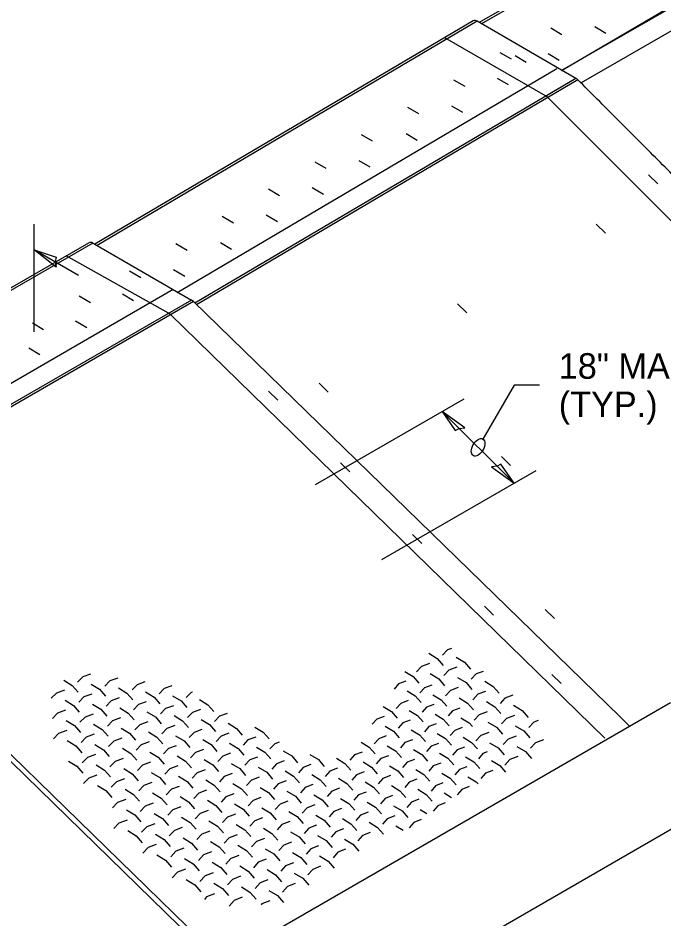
# Model space of a CAD drawing. Extents: x 99862 to 103151, y 100000 to 102076.
# Drawn here: x 101226 to 101630, y 101228 to 101791 of the extents above; entities that cross this region are included whole.
import ezdxf

# ---------------------------------------------------------------- set-up
doc = ezdxf.new("R2010")
doc.units = 0
for name, color, linetype in [('Level 11', 7, 'Continuous'), ('Level 15', 7, 'Continuous'), ('Level 20', 7, 'Continuous'), ('Level 3', 7, 'Continuous'), ('Level 36', 7, 'Continuous'), ('Level 4', 7, 'Continuous'), ('Level 5', 7, 'Continuous'), ('Level 7', 7, 'Continuous')]:
    doc.layers.add(name, color=color, linetype=linetype)

msp = doc.modelspace()

# ---------------------------------------------------------------- linework, layer by layer
at = {"layer": 'Level 11'}
for points in [[(101483.29, 101393.94), (101488.6, 101390.69), (101492.28, 101386.41)], [(101497.51, 101397), (101494.97, 101396.07), (101491.83, 101392.75)], [(101483.73, 101387.59), (101478.77, 101385.75), (101475.59, 101382.4)], [(101500.35, 101391.57), (101505.65, 101388.32), (101509.34, 101384.05)], [(101271.83, 101380.92), (101266.86, 101379.16), (101263.67, 101375.91)], [(101468.35, 101382.52), (101473.46, 101379.4), (101477.1, 101375.3)], [(101484.17, 101381.22), (101489.49, 101377.96), (101493.19, 101373.66)], [(101500.82, 101385.23), (101495.88, 101383.39), (101492.74, 101380.04)], [(101517.26, 101382.65), (101512.93, 101381.04), (101509.82, 101377.69)], [(101255.11, 101377.14), (101260.39, 101373.91), (101264.03, 101369.67)], [(101288.84, 101378.47), (101283.9, 101376.72), (101280.74, 101373.47)], [(101305.79, 101376.03), (101300.88, 101374.28), (101297.74, 101371.04)], [(101469.02, 101376.49), (101464.42, 101374.78), (101461.57, 101371.62)], [(101501.28, 101378.87), (101506.6, 101375.62), (101510.3, 101371.32)], [(101518.33, 101376.52), (101523.63, 101373.28), (101527.33, 101368.99)], [(101255.46, 101370.89), (101250.45, 101369.11), (101247.21, 101365.83)], [(101272.21, 101374.69), (101277.48, 101371.46), (101281.13, 101367.23)], [(101289.25, 101372.25), (101294.51, 101369.03), (101298.16, 101364.8)], [(101306.22, 101369.82), (101311.47, 101366.61), (101315.12, 101362.39)], [(101322.67, 101373.6), (101317.79, 101371.85), (101314.68, 101368.61)], [(101335.45, 101369.73), (101334.63, 101369.43), (101331.55, 101366.2)], [(101469.68, 101370.43), (101474.81, 101367.3), (101478.46, 101363.18)], [(101485.17, 101374.12), (101480.6, 101372.41), (101477.78, 101369.25)], [(101501.75, 101372.49), (101496.8, 101370.63), (101493.65, 101367.26)], [(101518.82, 101370.15), (101513.9, 101368.3), (101510.78, 101364.93)], [(101255.81, 101364.61), (101261.11, 101361.37), (101264.77, 101357.11)], [(101272.59, 101368.45), (101267.61, 101366.67), (101264.4, 101363.4)], [(101289.65, 101366.02), (101284.7, 101364.24), (101281.52, 101360.97)], [(101306.65, 101363.59), (101301.72, 101361.82), (101298.58, 101358.55)], [(101323.12, 101367.4), (101328.36, 101364.19), (101332.02, 101359.98)], [(101339.96, 101364.99), (101345.19, 101361.79), (101348.85, 101357.58)], [(101470.35, 101364.36), (101465.75, 101362.64), (101462.89, 101359.45)], [(101485.86, 101368.07), (101490.98, 101364.94), (101494.63, 101360.84)], [(101502.22, 101366.09), (101507.55, 101362.83), (101511.26, 101358.51)], [(101519.32, 101363.76), (101524.64, 101360.51), (101528.35, 101356.2)], [(101535.83, 101367.83), (101530.94, 101365.97), (101527.84, 101362.6)], [(101256.17, 101358.32), (101251.14, 101356.52), (101247.89, 101353.22)], [(101272.97, 101362.18), (101278.26, 101358.94), (101281.91, 101354.69)], [(101290.06, 101359.76), (101295.34, 101356.53), (101299, 101352.28)], [(101323.58, 101361.18), (101318.68, 101359.41), (101315.56, 101356.14)], [(101340.44, 101358.78), (101335.58, 101357.01), (101332.49, 101353.74)], [(101454.74, 101360.63), (101459.9, 101357.48), (101463.55, 101353.33)], [(101471.02, 101358.27), (101476.17, 101355.13), (101479.83, 101350.99)], [(101486.55, 101362.01), (101481.97, 101360.28), (101479.14, 101357.1)], [(101502.69, 101359.67), (101498.14, 101357.94), (101495.34, 101354.76)], [(101536.35, 101361.45), (101541.66, 101358.2), (101545.38, 101353.89)], [(101273.35, 101355.9), (101268.35, 101354.1), (101265.14, 101350.8)], [(101290.46, 101353.48), (101285.5, 101351.69), (101282.31, 101348.39)], [(101307.08, 101357.35), (101312.35, 101354.12), (101316.01, 101349.88)], [(101324.03, 101354.94), (101329.29, 101351.72), (101332.96, 101347.49)], [(101340.92, 101352.55), (101346.18, 101349.33), (101349.84, 101345.11)], [(101357.24, 101356.39), (101352.41, 101354.62), (101349.35, 101351.35)], [(101455.39, 101354.51), (101450.74, 101352.76), (101447.85, 101349.55)], [(101471.7, 101352.16), (101467.08, 101350.42), (101464.22, 101347.2)], [(101487.25, 101355.93), (101492.38, 101352.79), (101496.04, 101348.66)], [(101503.41, 101353.59), (101508.54, 101350.46), (101510.66, 101348.07)], [(101519.82, 101357.35), (101514.88, 101355.48), (101511.75, 101352.07)], [(101536.87, 101355.05), (101531.97, 101353.17), (101528.86, 101349.77)], [(101256.52, 101352.01), (101261.84, 101348.75), (101265.51, 101344.47)], [(101273.73, 101349.59), (101279.04, 101346.34), (101282.71, 101342.07)], [(101290.87, 101347.19), (101296.17, 101343.94), (101299.84, 101339.68)], [(101307.51, 101351.08), (101302.57, 101349.28), (101299.42, 101345.99)], [(101324.49, 101348.68), (101319.59, 101346.89), (101316.46, 101343.6)], [(101357.75, 101350.16), (101362.99, 101346.96), (101366.66, 101342.74)], [(101374.51, 101347.79), (101379.74, 101344.59), (101383.41, 101340.37)], [(101456.04, 101348.37), (101461.21, 101345.21), (101464.88, 101341.05)], [(101487.94, 101349.83), (101483.35, 101348.08), (101480.52, 101344.87)], [(101504.13, 101347.5), (101499.57, 101345.75), (101496.76, 101342.54)], [(101520.31, 101350.92), (101525.65, 101347.65), (101529.38, 101343.32)], [(101537.4, 101348.62), (101542.72, 101345.36), (101546.45, 101341.04)], [(101551.71, 101351.92), (101548.99, 101350.87), (101545.91, 101347.48)], [(101256.88, 101345.67), (101251.84, 101343.86), (101248.58, 101340.52)], [(101274.11, 101343.27), (101269.1, 101341.45), (101265.88, 101338.12)], [(101291.28, 101340.87), (101286.3, 101339.06), (101283.1, 101335.73)], [(101307.95, 101344.79), (101313.23, 101341.55), (101316.91, 101337.29)], [(101324.95, 101342.4), (101330.23, 101339.17), (101333.91, 101334.92)], [(101341.41, 101346.3), (101336.53, 101344.5), (101333.43, 101341.21)], [(101358.26, 101343.92), (101353.41, 101342.13), (101350.34, 101338.84)], [(101375.05, 101341.55), (101370.23, 101339.76), (101367.18, 101336.48)], [(101456.7, 101342.22), (101452.04, 101340.45), (101449.14, 101337.21)], [(101472.37, 101346.03), (101477.54, 101342.88), (101481.21, 101338.73)], [(101488.64, 101343.71), (101493.8, 101340.56), (101497.47, 101336.41)], [(101504.85, 101341.38), (101510, 101338.24), (101513.67, 101334.1)], [(101520.83, 101344.5), (101515.89, 101342.62), (101512.76, 101339.22)], [(101537.92, 101342.18), (101533.01, 101340.28), (101529.89, 101336.86)], [(101257.24, 101339.32), (101262.57, 101336.05), (101266.25, 101331.75)], [(101274.5, 101336.92), (101279.82, 101333.66), (101283.5, 101329.37)], [(101308.38, 101338.48), (101303.43, 101336.67), (101300.26, 101333.34)], [(101325.42, 101336.1), (101320.49, 101334.29), (101317.36, 101330.97)], [(101341.9, 101340.03), (101347.16, 101336.8), (101350.84, 101332.55)], [(101358.77, 101337.66), (101364.03, 101334.44), (101367.71, 101330.2)], [(101375.58, 101335.3), (101380.83, 101332.09), (101384.51, 101327.85)], [(101389.75, 101338.44), (101386.98, 101337.4), (101383.96, 101334.12)], [(101440.91, 101338.37), (101446.11, 101335.2), (101449.79, 101331.01)], [(101457.35, 101336.04), (101462.54, 101332.87), (101466.22, 101328.69)], [(101473.05, 101339.89), (101468.42, 101338.12), (101465.55, 101334.88)], [(101489.35, 101337.57), (101484.74, 101335.8), (101481.9, 101332.56)], [(101505.58, 101335.25), (101501, 101333.49), (101498.19, 101330.26)], [(101521.34, 101338.01), (101526.68, 101334.74), (101530.41, 101330.41)], [(101538.45, 101335.72), (101543.79, 101332.44), (101547.54, 101328.1)], [(101554.97, 101339.9), (101550.08, 101338), (101546.99, 101334.58)], [(101274.89, 101330.56), (101269.86, 101328.72), (101266.62, 101325.36)], [(101291.69, 101334.53), (101297.01, 101331.28), (101300.69, 101326.99)], [(101308.82, 101332.16), (101314.12, 101328.91), (101317.81, 101324.63)], [(101325.88, 101329.79), (101331.17, 101326.54), (101334.86, 101322.27)], [(101342.38, 101333.74), (101337.49, 101331.92), (101334.38, 101328.6)], [(101359.28, 101331.38), (101354.42, 101329.56), (101351.34, 101326.25)], [(101392.33, 101332.95), (101397.57, 101329.74), (101401.25, 101325.52)], [(101409.01, 101330.61), (101414.24, 101327.41), (101417.93, 101323.19)], [(101441.55, 101332.17), (101436.84, 101330.38), (101433.91, 101327.11)], [(101458.01, 101329.85), (101453.34, 101328.06), (101450.43, 101324.79)], [(101473.73, 101333.72), (101478.91, 101330.56), (101482.59, 101326.38)], [(101490.05, 101331.41), (101495.22, 101328.25), (101498.9, 101324.08)], [(101519.84, 101332.21), (101517.2, 101331.19), (101514.41, 101327.96)], [(101257.96, 101326.55), (101263.31, 101323.28), (101267, 101318.95)], [(101275.27, 101324.17), (101280.61, 101320.9), (101284.31, 101316.58)], [(101292.11, 101328.18), (101287.11, 101326.34), (101283.9, 101322.99)], [(101309.26, 101325.81), (101304.29, 101323.97), (101301.12, 101320.62)], [(101342.87, 101327.43), (101348.16, 101324.19), (101351.85, 101319.92)], [(101359.8, 101325.07), (101365.07, 101321.84), (101368.77, 101317.58)], [(101376.12, 101329.02), (101371.29, 101327.21), (101368.24, 101323.9)], [(101392.89, 101326.68), (101388.09, 101324.87), (101385.07, 101321.56)], [(101409.6, 101324.35), (101404.83, 101322.54), (101401.83, 101319.24)], [(101425.63, 101328.28), (101430.85, 101325.08), (101434.54, 101320.87)], [(101442.18, 101325.95), (101447.39, 101322.76), (101451.08, 101318.56)], [(101474.41, 101327.54), (101469.77, 101325.75), (101466.89, 101322.48)], [(101490.76, 101325.23), (101486.14, 101323.45), (101483.29, 101320.18)], [(101506.31, 101329.1), (101511.46, 101325.95), (101515.15, 101321.79)], [(101522.5, 101326.81), (101527.65, 101323.66), (101531.34, 101319.51)], [(101538.97, 101329.29), (101534.04, 101327.41), (101530.9, 101324.01)], [(101292.52, 101321.8), (101297.85, 101318.54), (101301.55, 101314.23)], [(101309.7, 101319.44), (101315.02, 101316.18), (101318.72, 101311.88)], [(101326.34, 101323.45), (101321.41, 101321.61), (101318.26, 101318.26)], [(101343.36, 101321.09), (101338.46, 101319.26), (101335.34, 101315.91)], [(101360.32, 101318.75), (101355.44, 101316.92), (101352.35, 101313.58)], [(101376.66, 101322.73), (101381.93, 101319.51), (101385.62, 101315.26)], [(101393.46, 101320.4), (101398.71, 101317.18), (101402.41, 101312.94)], [(101426.24, 101322.03), (101421.5, 101320.22), (101418.53, 101316.92)], [(101442.82, 101319.71), (101438.11, 101317.9), (101435.17, 101314.6)], [(101458.67, 101323.64), (101463.87, 101320.46), (101467.57, 101316.26)], [(101475.1, 101321.33), (101480.29, 101318.16), (101483.99, 101313.96)], [(101491.46, 101319.04), (101496.65, 101315.87), (101500.35, 101311.68)], [(101507.04, 101322.94), (101502.45, 101321.15), (101499.62, 101317.89)], [(101523.25, 101320.65), (101518.69, 101318.86), (101515.9, 101315.61)], [(101275.66, 101317.77), (101270.62, 101315.91), (101267.37, 101312.52)], [(101292.93, 101315.4), (101287.92, 101313.55), (101284.71, 101310.16)], [(101310.14, 101313.05), (101305.16, 101311.2), (101301.97, 101307.81)], [(101326.81, 101317.09), (101332.12, 101313.84), (101335.82, 101309.54)], [(101343.85, 101314.74), (101349.16, 101311.5), (101352.86, 101307.21)], [(101377.2, 101316.42), (101372.36, 101314.59), (101369.3, 101311.25)], [(101394.02, 101314.09), (101389.21, 101312.26), (101386.18, 101308.93)], [(101410.19, 101318.07), (101415.44, 101314.86), (101419.14, 101310.62)], [(101426.86, 101315.76), (101432.09, 101312.55), (101435.79, 101308.32)], [(101443.46, 101313.45), (101448.69, 101310.25), (101452.39, 101306.03)], [(101459.33, 101317.41), (101454.65, 101315.6), (101451.74, 101312.3)], [(101475.79, 101315.11), (101471.13, 101313.3), (101468.24, 101310.01)], [(101492.17, 101312.82), (101487.55, 101311.01), (101484.69, 101307.73)], [(101507.77, 101316.75), (101512.94, 101313.58), (101514.17, 101312.2)], [(101276.05, 101311.34), (101281.41, 101308.06), (101285.11, 101303.72)], [(101293.35, 101308.99), (101298.7, 101305.71), (101302.41, 101301.38)], [(101327.28, 101310.71), (101322.33, 101308.85), (101319.17, 101305.48)], [(101344.35, 101308.37), (101339.43, 101306.52), (101336.3, 101303.15)], [(101360.83, 101312.41), (101366.12, 101309.17), (101369.83, 101304.89)], [(101377.75, 101310.09), (101383.03, 101306.85), (101386.74, 101302.58)], [(101394.59, 101307.77), (101399.87, 101304.54), (101403.58, 101300.28)], [(101410.78, 101311.78), (101406, 101309.95), (101402.99, 101306.62)], [(101427.47, 101309.47), (101422.72, 101307.64), (101419.74, 101304.31)], [(101444.1, 101307.17), (101439.37, 101305.34), (101436.43, 101302.02)], [(101460, 101311.16), (101465.22, 101307.96), (101468.92, 101303.74)], [(101476.47, 101308.87), (101481.68, 101305.68), (101485.39, 101301.47)], [(101508.5, 101310.54), (101503.9, 101308.74), (101501.07, 101305.45)], [(101293.77, 101302.55), (101288.74, 101300.67), (101285.52, 101297.26)], [(101310.58, 101306.64), (101315.92, 101303.37), (101319.63, 101299.05)], [(101327.75, 101304.31), (101333.07, 101301.05), (101336.79, 101296.73)], [(101344.84, 101301.98), (101350.16, 101298.73), (101353.88, 101294.42)], [(101361.35, 101306.05), (101356.46, 101304.19), (101353.37, 101300.82)], [(101378.29, 101303.73), (101373.43, 101301.88), (101370.36, 101298.51)], [(101395.16, 101301.43), (101390.33, 101299.57), (101387.3, 101296.21)], [(101411.38, 101305.46), (101416.64, 101302.24), (101420.35, 101297.98)], [(101428.09, 101303.16), (101433.35, 101299.95), (101437.06, 101295.7)], [(101460.66, 101304.89), (101455.97, 101303.06), (101453.05, 101299.73)], [(101477.17, 101302.6), (101472.5, 101300.78), (101469.6, 101297.46)], [(101492.89, 101306.59), (101497.56, 101303.73)], [(101294.19, 101296.09), (101299.55, 101292.81), (101303.27, 101288.45)], [(101311.03, 101300.22), (101306.03, 101298.34), (101302.84, 101294.93)], [(101328.22, 101297.89), (101323.25, 101296.01), (101320.09, 101292.61)], [(101361.87, 101299.67), (101367.18, 101296.42), (101370.9, 101292.11)], [(101378.84, 101297.36), (101384.14, 101294.12), (101387.86, 101289.82)], [(101411.97, 101299.13), (101407.17, 101297.27), (101404.16, 101293.92)], [(101428.71, 101296.84), (101423.94, 101294.99), (101420.96, 101291.63)], [(101444.74, 101300.88), (101449.99, 101297.67), (101453.71, 101293.42)], [(101461.33, 101298.6), (101466.57, 101295.39), (101470.29, 101291.15)], [(101477.86, 101296.32), (101482.16, 101293.69)], [(101493.6, 101300.33), (101488.96, 101298.51), (101486.1, 101295.19)], [(101311.47, 101293.77), (101316.83, 101290.49), (101320.55, 101286.14)], [(101328.69, 101291.45), (101334.03, 101288.18), (101337.76, 101283.84)], [(101345.34, 101295.57), (101340.41, 101293.7), (101337.27, 101290.29)], [(101362.4, 101293.27), (101357.49, 101291.39), (101354.39, 101287.99)], [(101379.39, 101290.97), (101374.51, 101289.09), (101371.44, 101285.7)], [(101395.74, 101295.06), (101401.03, 101291.82), (101404.75, 101287.54)], [(101412.57, 101292.77), (101417.85, 101289.54), (101421.57, 101285.26)], [(101429.34, 101290.49), (101434.61, 101287.27), (101438.33, 101282.99)], [(101445.39, 101294.56), (101440.65, 101292.71), (101437.7, 101289.35)], [(101462, 101292.29), (101457.29, 101290.44), (101454.37, 101287.09)], [(101294.61, 101289.61), (101289.57, 101287.71), (101286.33, 101284.27)], [(101311.92, 101287.3), (101306.91, 101285.4), (101303.71, 101281.96)], [(101329.16, 101284.99), (101324.18, 101283.09), (101321.01, 101279.66)], [(101345.84, 101289.14), (101351.17, 101285.87), (101354.9, 101281.54)], [(101362.92, 101286.84), (101368.25, 101283.58), (101371.98, 101279.26)], [(101379.94, 101284.55), (101385.25, 101281.3), (101388.99, 101276.98)], [(101396.31, 101288.68), (101391.47, 101286.8), (101388.42, 101283.41)], [(101413.17, 101286.4), (101408.36, 101284.52), (101405.34, 101281.14)], [(101446.04, 101288.22), (101451.3, 101285), (101455.03, 101280.73)], [(101462.68, 101285.96), (101467.18, 101283.2)], [(101478.55, 101290.02), (101473.87, 101288.17), (101470.97, 101284.83)], [(101295.03, 101283.11), (101300.41, 101279.82), (101304.14, 101275.44)], [(101312.37, 101280.81), (101317.74, 101277.51), (101321.48, 101273.15)], [(101346.34, 101282.69), (101341.39, 101280.79), (101338.25, 101277.36)], [(101363.45, 101280.4), (101358.53, 101278.5), (101355.42, 101275.08)], [(101396.89, 101282.27), (101402.19, 101279.02), (101405.93, 101274.72)], [(101413.77, 101280), (101419.07, 101276.76), (101422.8, 101272.46)], [(101429.96, 101284.12), (101425.18, 101282.25), (101422.19, 101278.87)], [(101446.69, 101281.86), (101441.93, 101279.99), (101438.97, 101276.61)], [(101312.82, 101274.29), (101307.79, 101272.37), (101304.58, 101268.91)], [(101329.64, 101278.51), (101335, 101275.22), (101338.74, 101270.86)], [(101346.84, 101276.22), (101352.19, 101272.94), (101355.93, 101268.59)], [(101363.98, 101273.94), (101369.32, 101270.66), (101373.06, 101266.32)], [(101380.49, 101278.12), (101375.6, 101276.22), (101372.52, 101272.8)], [(101397.47, 101275.85), (101392.61, 101273.95), (101389.55, 101270.53)], [(101414.37, 101273.58), (101409.55, 101271.69), (101406.52, 101268.27)], [(101430.59, 101277.74), (101435.88, 101274.5), (101439.61, 101270.21)], [(101313.27, 101267.76), (101318.66, 101264.46), (101322.41, 101260.07)], [(101330.12, 101272), (101325.12, 101270.08), (101321.94, 101266.62)], [(101347.34, 101269.72), (101342.38, 101267.8), (101339.23, 101264.35)], [(101381.04, 101271.67), (101386.38, 101268.4), (101390.12, 101264.06)], [(101398.05, 101269.4), (101403.37, 101266.14), (101407.12, 101261.81)], [(101431.22, 101271.33), (101426.42, 101269.44), (101423.42, 101266.03)], [(101330.59, 101265.48), (101335.97, 101262.19), (101339.72, 101257.81)], [(101347.85, 101263.21), (101353.22, 101259.92), (101356.97, 101255.55)], [(101364.51, 101267.45), (101359.57, 101265.53), (101356.45, 101262.08)], [(101381.6, 101265.19), (101376.7, 101263.27), (101373.61, 101259.82)], [(101398.63, 101262.94), (101393.76, 101261.02), (101390.69, 101257.57)], [(101414.98, 101267.15), (101420.29, 101263.9), (101424.04, 101259.57)], [(101331.07, 101258.94), (101326.06, 101256.99), (101322.87, 101253.5)], [(101348.36, 101256.68), (101343.38, 101254.73), (101340.22, 101251.25)], [(101365.04, 101260.95), (101370.4, 101257.67), (101374.15, 101253.3)], [(101382.16, 101258.7), (101387.51, 101255.42), (101391.26, 101251.06)], [(101399.21, 101256.45), (101404.55, 101253.18), (101408.31, 101248.83)], [(101415.59, 101260.69), (101410.75, 101258.78), (101407.71, 101255.33)], [(101331.56, 101252.37), (101336.95, 101249.07), (101340.71, 101244.66)], [(101365.57, 101254.42), (101360.62, 101252.48), (101357.49, 101249)], [(101382.72, 101252.18), (101377.8, 101250.24), (101374.7, 101246.76)], [(101348.86, 101250.12), (101354.25, 101246.82), (101358.02, 101242.43)], [(101366.11, 101247.88), (101371.48, 101244.58), (101375.25, 101240.2)], [(101383.28, 101245.64), (101388.64, 101242.35), (101392.41, 101237.97)], [(101399.8, 101249.94), (101394.91, 101248), (101391.84, 101244.53)], [(101349.37, 101243.54), (101344.38, 101241.58), (101342.96, 101239.99)], [(101366.64, 101241.31), (101361.68, 101239.34), (101358.54, 101235.83)], [(101383.84, 101239.08), (101378.91, 101237.12), (101378.42, 101236.57)]]:
    msp.add_lwpolyline(points, dxfattribs=at)
at = {"layer": 'Level 15'}
for p, q in [((101236.6, 101595.01), (101236.6, 101662.51)), ((101264.17, 101630.26), (101236.6, 101646.51)), ((101536.59, 101561.75), (101517.11, 101528.02)), ((101552.59, 101561.75), (101536.59, 101561.75)), ((101412.41, 101499.51), (101505.48, 101553.25)), ((101491.62, 101545.25), (101536.6, 101500.41)), ((101453.91, 101452.67), (101550.46, 101508.41))]:
    msp.add_line(p, q, dxfattribs=at)
for points in [[(101236.6, 101646.51), (101250.22, 101641.73), (101249.59, 101639.01), (101250.22, 101635.56)], [(101491.62, 101545.25), (101499.78, 101533.34), (101502.25, 101534.65), (101505.74, 101534.94)], [(101536.6, 101500.41), (101528.44, 101512.31), (101525.98, 101511), (101522.48, 101510.71)]]:
    msp.add_lwpolyline(points, close=True, dxfattribs=at)
msp.add_ellipse((101514.11, 101522.83), major_axis=(3, 5.2), ratio=0.57735, dxfattribs=at)
at = {"layer": 'Level 3'}
for p, q in [((101273.2, 101650.61), (101018.64, 101503.64)), ((101030.62, 101512.24), (101270.7, 101650.85)), ((101273.2, 101650.61), (101274.41, 101649.9)), ((101274.41, 101649.9), (101334.93, 101614.92)), ((101334.93, 101614.92), (101080.37, 101467.95)), ((101336.08, 101614.04), (101081.52, 101467.07)), ((101336.08, 101614.04), (101602.84, 101354.32)), ((101348.28, 101207.36), (101081.52, 101467.07)), ((101081.55, 101462.94), (101347.07, 101204.22)), ((101634.49, 101362.93), (101379.93, 101215.96)), ((101602.84, 101354.32), (101608.98, 101348.2)), ((101413.08, 101155.93), (101667.64, 101302.9)), ((101413.08, 101155.93), (101667.64, 101302.9))]:
    msp.add_line(p, q, dxfattribs=at)
for centre, start_param, end_param in [((101273.2, 101646.52), 2.356194, 3.141593), ((101334.93, 101610.84), 2.025645, 2.356194)]:
    msp.add_ellipse(centre, major_axis=(2.5, -4.33), ratio=0.57735, start_param=start_param, end_param=end_param, dxfattribs=at)
at = {"layer": 'Level 36'}
for p, q in [((101559.62, 101785.33), (101566.57, 101781.23)), ((101587.14, 101786.18), (101594.1, 101782.08)), ((101527.79, 101769.93), (101534.75, 101765.83)), ((101537.24, 101768.04), (101544.19, 101763.94)), ((101557.87, 101769.28), (101564.83, 101765.18)), ((101498.85, 101752.84), (101505.81, 101748.74)), ((101526.07, 101753.87), (101533.02, 101749.77)), ((101469.91, 101735.75), (101476.86, 101731.65)), ((101497.5, 101736.56), (101504.46, 101732.46)), ((101440.96, 101718.67), (101447.92, 101714.57)), ((101469.05, 101719.18), (101476, 101715.08)), ((101439.57, 101702.41), (101446.53, 101698.31)), ((101412.02, 101701.58), (101418.97, 101697.48)), ((101620.68, 101693.25), (101626.47, 101687.62)), ((101410.41, 101685.45), (101417.37, 101681.35)), ((101383.07, 101684.49), (101390.03, 101680.39)), ((101381.65, 101668.25), (101388.61, 101664.15)), ((101354.13, 101667.41), (101361.09, 101663.3)), ((101588.04, 101662.58), (101593.83, 101656.95)), ((101353.03, 101650.98), (101359.98, 101646.88)), ((101325.19, 101650.32), (101332.14, 101646.22)), ((101323.74, 101634.09), (101330.7, 101629.99)), ((101296.24, 101633.23), (101303.2, 101629.13)), ((101264.74, 101617.65), (101271.7, 101613.55)), ((101291.7, 101618.83), (101298.65, 101614.73)), ((101501.35, 101612.73), (101507.14, 101607.1)), ((101235.46, 101600.77), (101242.41, 101596.67)), ((101262.41, 101601.95), (101269.37, 101597.85)), ((101233.12, 101585.06), (101240.08, 101580.96)), ((101414.66, 101562.89), (101420.44, 101557.26)), ((101383.13, 101557.9), (101388.92, 101552.27)), ((101528.69, 101517.08), (101534.48, 101511.45)), ((101428.11, 101513.06), (101433.9, 101507.43)), ((101473.08, 101468.22), (101478.87, 101462.59)), ((101518.06, 101423.38), (101523.85, 101417.75)), ((101556.02, 101421.42), (101561.81, 101415.79)), ((101560.23, 101380.65), (101566.02, 101375.02))]:
    msp.add_line(p, q, dxfattribs=at)
at = {"layer": 'Level 4'}
for p, q in [((101511.11, 101789.66), (101274.41, 101649.9)), ((101513.61, 101789.41), (101275.88, 101649.06)), ((101575.35, 101753.72), (101513.61, 101789.41)), ((101575.35, 101753.72), (101337.08, 101613.07)), ((101576.5, 101752.84), (101338.07, 101612.1))]:
    msp.add_line(p, q, dxfattribs=at)
for centre, start_param, end_param in [((101513.61, 101785.33), 2.356194, 3.141593), ((101575.35, 101749.64), 2.025645, 2.356194)]:
    msp.add_ellipse(centre, major_axis=(2.5, -4.33), ratio=0.57735, start_param=start_param, end_param=end_param, dxfattribs=at)
msp.add_open_spline([(101953.72, 101371.89), (101768.44, 101560.71), (101576.5, 101752.84)], degree=2, dxfattribs=at)
at = {"layer": 'Level 5'}
for p, q in [((101751.53, 101925.37), (101514.83, 101788.71)), ((101754.03, 101925.12), (101516.29, 101787.86)), ((101804.6, 101896.19), (101566.32, 101758.63)), ((101816.91, 101888.55), (101578.49, 101750.9))]:
    msp.add_line(p, q, dxfattribs=at)
at = {"layer": 'Level 7'}
for p, q in [((101566.32, 101758.63), (101801.43, 101897.41)), ((101556.36, 101742.76), (101493.33, 101779.16)), ((101325.91, 101619.82), (101563.32, 101759.97)), ((102341.08, 100957.72), (101557.51, 101741.88)), ((101320.59, 101606.84), (101256.6, 101642.71)), ((101069.2, 101474.71), (101323.52, 101621.91)), ((101593.41, 101340.88), (101321.75, 101605.97))]:
    msp.add_line(p, q, dxfattribs=at)
for centre, major_axis in [((101556.36, 101738.68), (2.5, -4.33)), ((101320.64, 101602.76), (2.55, -4.3))]:
    msp.add_ellipse(centre, major_axis=major_axis, ratio=0.57735, start_param=2.025645, end_param=2.356194, dxfattribs=at)

# ---------------------------------------------------------------- texts
at = {"layer": 'Level 20'}
for s, p in [('18" MAX.', (101564.58, 101565.75)), ('(TYP.)', (101564.58, 101541.75))]:
    msp.add_text(s, height=16, dxfattribs=at).set_placement(p)

doc.saveas('drawing.dxf')
